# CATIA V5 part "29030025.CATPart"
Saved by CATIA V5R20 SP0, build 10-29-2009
Part number: 29030025
Definition: NONE
Nomenclature: 29030025
Source: Unknown
Description: 29030025
Bounding box of the stored display mesh (mm): x -12.5 to 44.548, y -29 to 63.548, z -19 to 19
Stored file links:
  C:\Users\Utente\Desktop\IO LAVORO\3D X SITO CF\X SITO\PLASTICA\RF1\29030025.CATPart
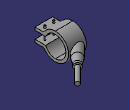
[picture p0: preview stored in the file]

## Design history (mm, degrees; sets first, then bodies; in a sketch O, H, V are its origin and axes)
Body1 "29030025" (main body)
  Solid1: solid without history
